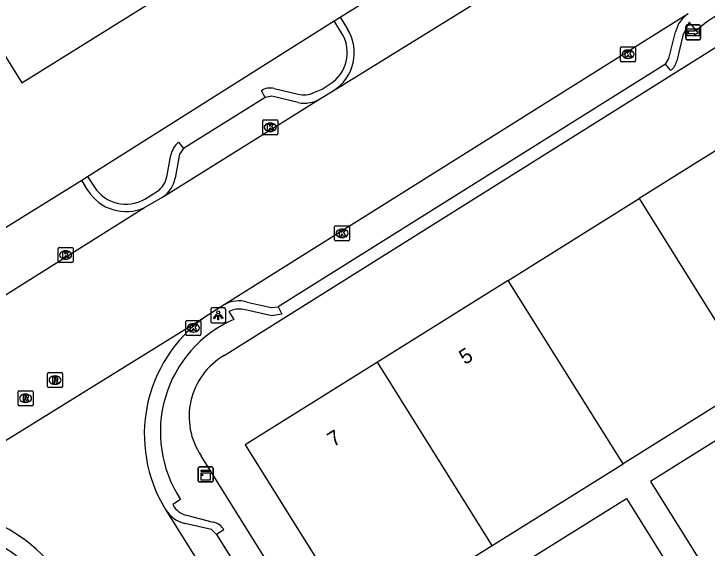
# Model space of a CAD drawing. Extents: x 158461 to 159795, y 387220 to 388672.
# Drawn here: x 158716.21 to 158762.56, y 387859.14 to 387894.88 of the extents above; entities that cross this region are included whole.
import ezdxf

# ---------------------------------------------------------------- set-up
doc = ezdxf.new("R2010")
doc.units = 0
for name, color, linetype in [('IMGEO_Kast', 7, 'Continuous'), ('IMGEO_Kolk', 7, 'Continuous'), ('IMGEO_Lichtpunt', 7, 'Continuous'), ('IMGEO_Pand', 7, 'Continuous'), ('IMGEO_Pand_nummerreeks', 7, 'Continuous'), ('IMGEO_Rijbaan_lokaal_gesloten', 7, 'Continuous'), ('IMGEO_Rioolput', 7, 'Continuous'), ('IMGEO_Voetpad_open', 7, 'Continuous'), ('IMGEO_Wegwijzer', 7, 'Continuous')]:
    doc.layers.add(name, color=color, linetype=linetype)

msp = doc.modelspace()

# ---------------------------------------------------------------- linework, layer by layer
at = {"layer": 'IMGEO_Kast'}
for p, q in [((158728.604, 387864.573), (158729.445, 387864.573)), ((158729.445, 387864.573), (158728.604, 387864.573)), ((158728.529, 387863.648), (158728.529, 387864.489)), ((158728.529, 387864.489), (158728.529, 387863.648)), ((158729.529, 387864.498), (158729.529, 387863.657)), ((158729.529, 387863.657), (158729.529, 387864.498)), ((158729.454, 387863.573), (158728.613, 387863.573)), ((158728.613, 387863.573), (158729.454, 387863.573))]:
    msp.add_line(p, q, dxfattribs=at)
for points in [[(158728.724, 387864.363), (158729.324, 387864.363), (158729.324, 387864.278), (158728.724, 387864.278), (158728.724, 387864.363)], [(158728.724, 387864.188), (158729.324, 387864.188), (158729.324, 387863.699), (158728.724, 387863.699), (158728.724, 387864.188)]]:
    msp.add_lwpolyline(points, dxfattribs=at)
msp.add_circle((158728.808, 387864.037), 0.0377, dxfattribs=at)
for centre, start, end in [((158728.607, 387864.495), 92.4484, 184.2845), ((158728.607, 387864.495), 92.4484, 184.2845), ((158729.451, 387864.495), 2.4484, 94.2845), ((158729.451, 387864.495), 2.4484, 94.2845), ((158728.607, 387863.651), 182.4484, 274.2845), ((158728.607, 387863.651), 182.4484, 274.2845), ((158729.451, 387863.651), 272.4484, 4.2845), ((158729.451, 387863.651), 272.4484, 4.2845)]:
    msp.add_arc(centre, 0.0779, start, end, dxfattribs=at)
at = {"layer": 'IMGEO_Kolk'}
for p, q in [((158756.77, 387891.75), (158756.77, 387892.602)), ((158756.845, 387892.676), (158757.697, 387892.676)), ((158757.258, 387892.456), (158757.283, 387892.456)), ((158757.771, 387892.602), (158757.771, 387891.75)), ((158757.281, 387891.896), (158757.256, 387891.896)), ((158757.697, 387891.676), (158756.845, 387891.676)), ((158732.924, 387887.789), (158733.776, 387887.789)), ((158732.849, 387886.863), (158732.849, 387887.715)), ((158733.337, 387887.569), (158733.362, 387887.569)), ((158733.85, 387887.715), (158733.85, 387886.863)), ((158733.36, 387887.009), (158733.335, 387887.009)), ((158733.776, 387886.789), (158732.924, 387886.789)), ((158737.654, 387879.771), (158737.654, 387880.623)), ((158737.729, 387880.697), (158738.581, 387880.697)), ((158738.142, 387880.477), (158738.167, 387880.477)), ((158738.655, 387880.623), (158738.655, 387879.771)), ((158738.165, 387879.917), (158738.14, 387879.917)), ((158738.581, 387879.697), (158737.729, 387879.697)), ((158719.167, 387878.324), (158719.167, 387879.176)), ((158719.242, 387879.25), (158720.094, 387879.25)), ((158719.655, 387879.03), (158719.68, 387879.03)), ((158720.168, 387879.176), (158720.168, 387878.324)), ((158719.678, 387878.47), (158719.653, 387878.47)), ((158720.094, 387878.25), (158719.242, 387878.25)), ((158727.707, 387873.446), (158727.707, 387874.298)), ((158727.782, 387874.372), (158728.634, 387874.372)), ((158728.708, 387874.298), (158728.708, 387873.446)), ((158728.195, 387874.152), (158728.22, 387874.152)), ((158728.634, 387873.372), (158727.782, 387873.372)), ((158728.218, 387873.592), (158728.193, 387873.592))]:
    msp.add_line(p, q, dxfattribs=at)
for points in [[(158756.77, 387891.75), (158756.77, 387892.602)], [(158756.845, 387892.676), (158757.697, 387892.676)], [(158757.091, 387892.376), (158757.214, 387892.376), (158757.214, 387892.225), (158757.344, 387892.376), (158757.508, 387892.376), (158757.362, 387892.225), (158757.515, 387891.976), (158757.363, 387891.976), (158757.278, 387892.14), (158757.214, 387892.073), (158757.214, 387891.976), (158757.091, 387891.976), (158757.091, 387892.376)], [(158757.771, 387892.602), (158757.771, 387891.75)], [(158757.697, 387891.676), (158756.845, 387891.676)], [(158732.924, 387887.789), (158733.776, 387887.789)], [(158732.849, 387886.863), (158732.849, 387887.715)], [(158733.17, 387887.489), (158733.293, 387887.489), (158733.293, 387887.338), (158733.423, 387887.489), (158733.587, 387887.489), (158733.441, 387887.338), (158733.594, 387887.089), (158733.442, 387887.089), (158733.357, 387887.253), (158733.293, 387887.186), (158733.293, 387887.089), (158733.17, 387887.089), (158733.17, 387887.489)], [(158733.85, 387887.715), (158733.85, 387886.863)], [(158733.776, 387886.789), (158732.924, 387886.789)], [(158737.654, 387879.771), (158737.654, 387880.623)], [(158737.729, 387880.697), (158738.581, 387880.697)], [(158737.975, 387880.397), (158738.098, 387880.397), (158738.098, 387880.246), (158738.228, 387880.397), (158738.392, 387880.397), (158738.246, 387880.246), (158738.399, 387879.997), (158738.247, 387879.997), (158738.162, 387880.161), (158738.098, 387880.094), (158738.098, 387879.997), (158737.975, 387879.997), (158737.975, 387880.397)], [(158738.655, 387880.623), (158738.655, 387879.771)], [(158738.581, 387879.697), (158737.729, 387879.697)], [(158719.167, 387878.324), (158719.167, 387879.176)], [(158719.242, 387879.25), (158720.094, 387879.25)], [(158719.488, 387878.95), (158719.611, 387878.95), (158719.611, 387878.799), (158719.741, 387878.95), (158719.905, 387878.95), (158719.759, 387878.799), (158719.912, 387878.55), (158719.76, 387878.55), (158719.675, 387878.714), (158719.611, 387878.647), (158719.611, 387878.55), (158719.488, 387878.55), (158719.488, 387878.95)], [(158720.168, 387879.176), (158720.168, 387878.324)], [(158720.094, 387878.25), (158719.242, 387878.25)], [(158727.707, 387873.446), (158727.707, 387874.298)], [(158727.782, 387874.372), (158728.634, 387874.372)], [(158728.708, 387874.298), (158728.708, 387873.446)], [(158728.028, 387874.072), (158728.151, 387874.072), (158728.151, 387873.921), (158728.281, 387874.072), (158728.445, 387874.072), (158728.299, 387873.921), (158728.452, 387873.672), (158728.3, 387873.672), (158728.215, 387873.836), (158728.151, 387873.769), (158728.151, 387873.672), (158728.028, 387873.672), (158728.028, 387874.072)], [(158728.634, 387873.372), (158727.782, 387873.372)]]:
    msp.add_lwpolyline(points, dxfattribs=at)
for centre, start, end in [((158756.847, 387892.6), 91.552, 178.448), ((158756.847, 387892.6), 91.552, 178.448), ((158757.695, 387892.6), 1.552, 88.448), ((158757.695, 387892.6), 1.552, 88.448), ((158756.847, 387891.752), 181.552, 268.448), ((158756.847, 387891.752), 181.552, 268.448), ((158757.695, 387891.752), 271.552, 358.448), ((158757.695, 387891.752), 271.552, 358.448), ((158732.926, 387887.713), 91.552, 178.448), ((158732.926, 387887.713), 91.552, 178.448), ((158733.774, 387887.713), 1.552, 88.448), ((158733.774, 387887.713), 1.552, 88.448), ((158732.926, 387886.865), 181.552, 268.448), ((158732.926, 387886.865), 181.552, 268.448), ((158733.774, 387886.865), 271.552, 358.448), ((158733.774, 387886.865), 271.552, 358.448), ((158737.731, 387880.621), 91.552, 178.448), ((158737.731, 387880.621), 91.552, 178.448), ((158738.579, 387880.621), 1.552, 88.448), ((158738.579, 387880.621), 1.552, 88.448), ((158737.731, 387879.773), 181.552, 268.448), ((158737.731, 387879.773), 181.552, 268.448), ((158738.579, 387879.773), 271.552, 358.448), ((158738.579, 387879.773), 271.552, 358.448), ((158719.244, 387879.174), 91.552, 178.448), ((158719.244, 387879.174), 91.552, 178.448), ((158720.092, 387879.174), 1.552, 88.448), ((158720.092, 387879.174), 1.552, 88.448), ((158719.244, 387878.326), 181.552, 268.448), ((158719.244, 387878.326), 181.552, 268.448), ((158720.092, 387878.326), 271.552, 358.448), ((158720.092, 387878.326), 271.552, 358.448), ((158727.784, 387874.296), 91.552, 178.448), ((158727.784, 387874.296), 91.552, 178.448), ((158728.632, 387874.296), 1.552, 88.448), ((158728.632, 387874.296), 1.552, 88.448), ((158727.784, 387873.448), 181.552, 268.448), ((158727.784, 387873.448), 181.552, 268.448), ((158728.632, 387873.448), 271.552, 358.448), ((158728.632, 387873.448), 271.552, 358.448)]:
    msp.add_arc(centre, 0.0765, start, end, dxfattribs=at)
for centre, major_axis, ratio, start_param, end_param in [((158757.257, 387892.176), (-0.387, 0.002), 0.722429, 4.712389, 7.853982), ((158757.282, 387892.176), (-0.39, 0.002), 0.717154, 1.570796, 4.712389), ((158733.336, 387887.289), (-0.387, 0.002), 0.722429, 4.712389, 7.853982), ((158733.361, 387887.289), (-0.39, 0.002), 0.717154, 1.570796, 4.712389), ((158738.141, 387880.197), (-0.387, 0.002), 0.722429, 4.712389, 7.853982), ((158738.166, 387880.197), (-0.39, 0.002), 0.717154, 1.570796, 4.712389), ((158719.654, 387878.75), (-0.387, 0.002), 0.722429, 4.712389, 7.853982), ((158719.679, 387878.75), (-0.39, 0.002), 0.717154, 1.570796, 4.712389), ((158728.194, 387873.872), (-0.387, 0.002), 0.722429, 4.712389, 7.853982), ((158728.219, 387873.872), (-0.39, 0.002), 0.717154, 1.570796, 4.712389)]:
    msp.add_ellipse(centre, major_axis=major_axis, ratio=ratio, start_param=start_param, end_param=end_param, dxfattribs=at)
at = {"layer": 'IMGEO_Lichtpunt'}
for p, q in [((158730.277, 387875.21), (158729.469, 387875.21)), ((158730.277, 387875.21), (158729.469, 387875.21)), ((158729.375, 387875.115), (158729.375, 387874.308)), ((158729.375, 387875.115), (158729.375, 387874.308)), ((158730.371, 387874.308), (158730.371, 387875.115)), ((158730.371, 387874.308), (158730.371, 387875.115)), ((158729.469, 387874.214), (158730.277, 387874.214)), ((158729.469, 387874.214), (158730.277, 387874.214))]:
    msp.add_line(p, q, dxfattribs=at)
for points in [[(158729.749, 387874.779), (158729.788, 387874.751), (158729.6, 387874.489), (158729.562, 387874.516), (158729.749, 387874.779)], [(158729.961, 387874.751), (158729.999, 387874.778), (158730.186, 387874.516), (158730.147, 387874.488), (158729.961, 387874.751)], [(158729.851, 387874.731), (158729.898, 387874.731), (158729.898, 387874.409), (158729.851, 387874.409), (158729.851, 387874.731)]]:
    msp.add_lwpolyline(points, dxfattribs=at)
msp.add_circle((158729.874, 387874.913), 0.0994, dxfattribs=at)
for centre, start, end in [((158729.469, 387875.115), 90, 180), ((158729.469, 387875.115), 90, 180), ((158730.277, 387875.115), 0, 90), ((158730.277, 387875.115), 0, 90), ((158729.469, 387874.308), 180, 270), ((158729.469, 387874.308), 180, 270), ((158730.277, 387874.308), 270, 0), ((158730.277, 387874.308), 270, 360)]:
    msp.add_arc(centre, 0.0946, start, end, dxfattribs=at)
at = {"layer": 'IMGEO_Pand'}
for points in [[(158714.098, 387894.495), (158716.744, 387890.253), (158744.632, 387907.644), (158718.89, 387948.844), (158715.414, 387954.407), (158714.151, 387956.428), (158704.296, 387972.201), (158703.378, 387971.725), (158698.855, 387972.584), (158698.268, 387973.691)], [(158765.682, 387870.241), (158774.531, 387875.772), (158766.857, 387888.05), (158758.009, 387882.52)], [(158749.263, 387877.054), (158758.009, 387882.52)], [(158758.009, 387882.52), (158765.682, 387870.241)], [(158749.263, 387877.054), (158740.518, 387871.588)], [(158756.936, 387864.776), (158749.263, 387877.054)], [(158781.189, 387865.148), (158775.586, 387874.113), (158771.346, 387871.463), (158758.776, 387863.607), (158764.379, 387854.641)], [(158740.518, 387871.588), (158731.669, 387866.058), (158739.342, 387853.78), (158748.191, 387859.31)], [(158748.191, 387859.31), (158740.518, 387871.588)], [(158765.682, 387870.241), (158756.936, 387864.776)], [(158748.191, 387859.31), (158756.936, 387864.776)], [(158745.985, 387843.102), (158740.419, 387852.007), (158744.66, 387854.657), (158757.16, 387862.47), (158762.726, 387853.564)]]:
    msp.add_lwpolyline(points, dxfattribs=at)
at = {"layer": 'IMGEO_Rijbaan_lokaal_gesloten'}
for points in [[(158737.557, 387889.73), (158747.402, 387895.845)], [(158761.287, 387894.877), (158730.27, 387875.42)], [(158736.719, 387889.215), (158737.557, 387889.73)], [(158726.151, 387882.608), (158736.719, 387889.215)], [(158724.947, 387881.922), (158726.151, 387882.608)], [(158697.138, 387864.442), (158724.947, 387881.922)], [(158730.27, 387875.42), (158728.966, 387874.586)], [(158705.777, 387860.235), (158728.821, 387874.508), (158728.966, 387874.586)], [(158726.354, 387861.718), (158765.551, 387798.969)]]:
    msp.add_lwpolyline(points, dxfattribs=at)
for centre, radius, start, end in [((158767.6, 387887.416), 9.675, 26.5749, 123.7515), ((158734.55, 387866.753), 9.619, 125.4859, 211.5656), ((158710.959, 387851.68), 10.002, 39.7447, 121.2036)]:
    msp.add_arc(centre, radius, start, end, dxfattribs=at)
at = {"layer": 'IMGEO_Rioolput'}
for p, q in [((158718.463, 387869.958), (158718.463, 387870.81)), ((158718.538, 387870.884), (158719.39, 387870.884)), ((158718.951, 387870.664), (158718.976, 387870.664)), ((158719.464, 387870.81), (158719.464, 387869.958)), ((158716.564, 387869.666), (158717.416, 387869.666)), ((158719.39, 387869.884), (158718.538, 387869.884)), ((158718.974, 387870.104), (158718.949, 387870.104)), ((158716.489, 387868.74), (158716.489, 387869.592)), ((158716.977, 387869.446), (158717.002, 387869.446)), ((158717.49, 387869.592), (158717.49, 387868.74)), ((158717, 387868.886), (158716.975, 387868.886)), ((158717.416, 387868.666), (158716.564, 387868.666))]:
    msp.add_line(p, q, dxfattribs=at)
for points in [[(158718.463, 387869.958), (158718.463, 387870.81)], [(158718.538, 387870.884), (158719.39, 387870.884)], [(158719.052, 387870.582), (158718.8, 387870.584), (158718.8, 387870.184)], [(158719.464, 387870.81), (158719.464, 387869.958)], [(158718.8, 387870.184), (158718.924, 387870.184), (158718.924, 387870.346), (158718.935, 387870.346)], [(158718.978, 387870.503), (158718.924, 387870.503), (158718.924, 387870.422)], [(158718.924, 387870.422), (158718.976, 387870.422)], [(158718.982, 387870.317), (158719.053, 387870.184), (158719.193, 387870.184), (158719.128, 387870.31)], [(158716.564, 387869.666), (158717.416, 387869.666)], [(158719.39, 387869.884), (158718.538, 387869.884)], [(158716.489, 387868.74), (158716.489, 387869.592)], [(158717.078, 387869.364), (158716.826, 387869.366), (158716.826, 387868.966)], [(158717.004, 387869.285), (158716.95, 387869.285), (158716.95, 387869.204)], [(158716.95, 387869.204), (158717.002, 387869.204)], [(158717.49, 387869.592), (158717.49, 387868.74)], [(158716.826, 387868.966), (158716.95, 387868.966), (158716.95, 387869.128), (158716.961, 387869.128)], [(158717.008, 387869.099), (158717.079, 387868.966), (158717.219, 387868.966), (158717.154, 387869.092)], [(158717.416, 387868.666), (158716.564, 387868.666)]]:
    msp.add_lwpolyline(points, dxfattribs=at)
for centre, radius, start, end in [((158718.54, 387870.808), 0.0765, 91.552, 178.448), ((158718.54, 387870.808), 0.0765, 91.552, 178.448), ((158719.051, 387870.472), 0.109, 350.3612, 89.416), ((158719.388, 387870.808), 0.0765, 1.552, 88.448), ((158719.388, 387870.808), 0.0765, 1.552, 88.448), ((158718.934, 387870.293), 0.0533, 26.0293, 88.6989), ((158718.96, 387870.611), 0.19, 274.7715, 282.9687), ((158718.984, 387870.407), 0.0964, 77.0061, 93.1865), ((158718.998, 387870.464), 0.0378, 276.6634, 79.6772), ((158719.049, 387870.472), 0.112, 277.5842, 350.9817), ((158719.033, 387870.257), 0.108, 29.5134, 73.7905), ((158716.566, 387869.59), 0.0765, 91.552, 178.448), ((158716.566, 387869.59), 0.0765, 91.552, 178.448), ((158717.414, 387869.59), 0.0765, 1.552, 88.448), ((158717.414, 387869.59), 0.0765, 1.552, 88.448), ((158718.54, 387869.96), 0.0765, 181.552, 268.448), ((158718.54, 387869.96), 0.0765, 181.552, 268.448), ((158719.388, 387869.96), 0.0765, 271.552, 358.448), ((158719.388, 387869.96), 0.0765, 271.552, 358.448), ((158716.986, 387869.393), 0.19, 274.7715, 282.9687), ((158717.01, 387869.189), 0.0964, 77.0061, 93.1865), ((158717.024, 387869.246), 0.0378, 276.6634, 79.6772), ((158717.077, 387869.254), 0.109, 350.3612, 89.416), ((158717.075, 387869.254), 0.112, 277.5842, 350.9817), ((158716.566, 387868.742), 0.0765, 181.552, 268.448), ((158716.566, 387868.742), 0.0765, 181.552, 268.448), ((158716.96, 387869.075), 0.0533, 26.0293, 88.6989), ((158717.059, 387869.039), 0.108, 29.5134, 73.7905), ((158717.414, 387868.742), 0.0765, 271.552, 358.448), ((158717.414, 387868.742), 0.0765, 271.552, 358.448)]:
    msp.add_arc(centre, radius, start, end, dxfattribs=at)
for centre, major_axis, ratio, start_param, end_param in [((158718.95, 387870.384), (-0.387, 0.002), 0.722429, 4.712389, 7.853982), ((158718.975, 387870.384), (-0.39, 0.002), 0.717154, 1.570796, 4.712389), ((158716.976, 387869.166), (-0.387, 0.002), 0.722429, 4.712389, 7.853982), ((158717.001, 387869.166), (-0.39, 0.002), 0.717154, 1.570796, 4.712389)]:
    msp.add_ellipse(centre, major_axis=major_axis, ratio=ratio, start_param=start_param, end_param=end_param, dxfattribs=at)
at = {"layer": 'IMGEO_Voetpad_open'}
for points in [[(158738.014, 387894.663), (158743.631, 387898.186)], [(158721.126, 387883.994), (158737.622, 387894.417)], [(158730.264, 387872.022), (158765.776, 387894.3)], [(158737.622, 387894.417), (158738.014, 387894.663)], [(158738.178, 387893.505), (158737.622, 387894.417)], [(158738.014, 387894.663), (158738.517, 387893.864)], [(158761.841, 387893.765), (158761.369, 387894.314), (158760.928, 387893.436), (158760.538, 387891.731)], [(158759.784, 387891.52), (158760.011, 387891.896), (158760.452, 387893.681)], [(158759.784, 387891.52), (158733.887, 387875.283)], [(158760.117, 387891.103), (158759.784, 387891.52)], [(158736.256, 387889.608), (158736.824, 387889.845), (158737.357, 387890.195)], [(158733.006, 387889.285), (158732.757, 387889.727)], [(158733.614, 387889.885), (158735.216, 387889.508)], [(158733.006, 387889.285), (158727.552, 387885.868)], [(158735.219, 387888.944), (158733.462, 387889.364), (158733.006, 387889.285)], [(158727.212, 387886.301), (158727.552, 387885.868)], [(158726.435, 387883.976), (158726.704, 387885.42)], [(158727.552, 387885.868), (158727.273, 387885.486), (158726.991, 387883.889)], [(158697.447, 387869.303), (158720.745, 387883.755)], [(158720.745, 387883.755), (158721.126, 387883.994)], [(158721.157, 387883.073), (158720.745, 387883.755)], [(158721.126, 387883.994), (158721.598, 387883.281)], [(158724.955, 387882.483), (158725.821, 387883.029)], [(158733.887, 387875.283), (158734.133, 387874.803), (158733.455, 387874.675), (158731.578, 387875.105)], [(158731.815, 387875.59), (158733.413, 387875.231), (158733.887, 387875.283)], [(158730.588, 387874.973), (158730.914, 387874.446)], [(158743.767, 387841.201), (158728.733, 387865.314)], [(158727.358, 387862.389), (158726.831, 387862.058)], [(158727.76, 387861.339), (158729.524, 387860.886)], [(158729.75, 387860.062), (158729.422, 387860.387), (158727.644, 387860.794)], [(158730.255, 387860.368), (158729.75, 387860.062)], [(158729.75, 387860.062), (158742.164, 387840.209)]]:
    msp.add_lwpolyline(points, dxfattribs=at)
for centre, radius, start, end in [((158767.546, 387887.379), 8.563, 29.8265, 131.7755), ((158762.357, 387893.24), 1.956, 123.1839, 166.9736), ((158735.953, 387892.281), 3.014, 302.1678, 31.6851), ((158736.028, 387892.281), 2.474, 302.4978, 29.6416), ((158759.513, 387891.963), 1.051, 305.0912, 347.2344), ((158733.355, 387888.887), 1.031, 75.4457, 125.4463), ((158735.601, 387890.965), 1.507, 255.2113, 295.7733), ((158735.62, 387891.012), 2.107, 259.03, 301.4519), ((158728.293, 387885.091), 1.622, 131.7673, 168.2957), ((158724.955, 387884.263), 1.508, 305.0671, 349.0171), ((158724.996, 387884.281), 2.033, 304.6174, 348.8738), ((158723.701, 387884.667), 2.519, 213.397, 299.8595), ((158723.706, 387884.65), 2.997, 211.7408, 294.4728), ((158731.232, 387873.78), 1.902, 72.1603, 120.398), ((158731.285, 387873.526), 1.606, 79.475, 115.7143), ((158734.231, 387866.915), 8.229, 113.7716, 213.3634), ((158732.635, 387867.952), 4.71, 120.2268, 214.0599), ((158728.079, 387862.711), 1.409, 207.6159, 256.9079), ((158728.155, 387862.87), 2.138, 212.6076, 256.1659), ((158729.334, 387859.843), 1.06, 29.6723, 79.6835), ((158710.924, 387851.5), 8.959, 39.2543, 124.1196)]:
    msp.add_arc(centre, radius, start, end, dxfattribs=at)
at = {"layer": 'IMGEO_Wegwijzer'}
for p, q in [((158761.132, 387893.24), (158761.132, 387894.04)), ((158761.132, 387894.04), (158761.132, 387893.24)), ((158761.232, 387894.14), (158762.022, 387894.14)), ((158762.022, 387894.14), (158761.232, 387894.14)), ((158762.122, 387894.04), (158762.122, 387893.24)), ((158762.122, 387893.24), (158762.122, 387894.04)), ((158762.022, 387893.14), (158761.232, 387893.14)), ((158761.232, 387893.14), (158762.022, 387893.14))]:
    msp.add_line(p, q, dxfattribs=at)
for points in [[(158761.233, 387893.872), (158762.021, 387893.872), (158762.021, 387893.408), (158761.233, 387893.408), (158761.233, 387893.872)], [(158761.298, 387893.724), (158761.298, 387893.64), (158761.298, 387893.556), (158761.709, 387893.556), (158761.709, 387893.473), (158761.956, 387893.64), (158761.709, 387893.807), (158761.709, 387893.724), (158761.298, 387893.724)]]:
    msp.add_lwpolyline(points, dxfattribs=at)
for centre, start, end in [((158761.232, 387894.04), 90, 180), ((158761.232, 387894.04), 90, 180), ((158762.022, 387894.04), 0, 90), ((158762.022, 387894.04), 360, 90), ((158761.232, 387893.24), 180, 270), ((158761.232, 387893.24), 180, 270), ((158762.022, 387893.24), 270, 0), ((158762.022, 387893.24), 270, 0)]:
    msp.add_arc(centre, 0.1, start, end, dxfattribs=at)

# ---------------------------------------------------------------- texts
at = {"layer": 'IMGEO_Pand_nummerreeks'}
for s, p in [('5', (158746.369, 387871.378)), ('7', (158737.572, 387865.88))]:
    msp.add_text(s, height=1, rotation=32.0048, dxfattribs=at).set_placement(p)

doc.saveas('drawing.dxf')
